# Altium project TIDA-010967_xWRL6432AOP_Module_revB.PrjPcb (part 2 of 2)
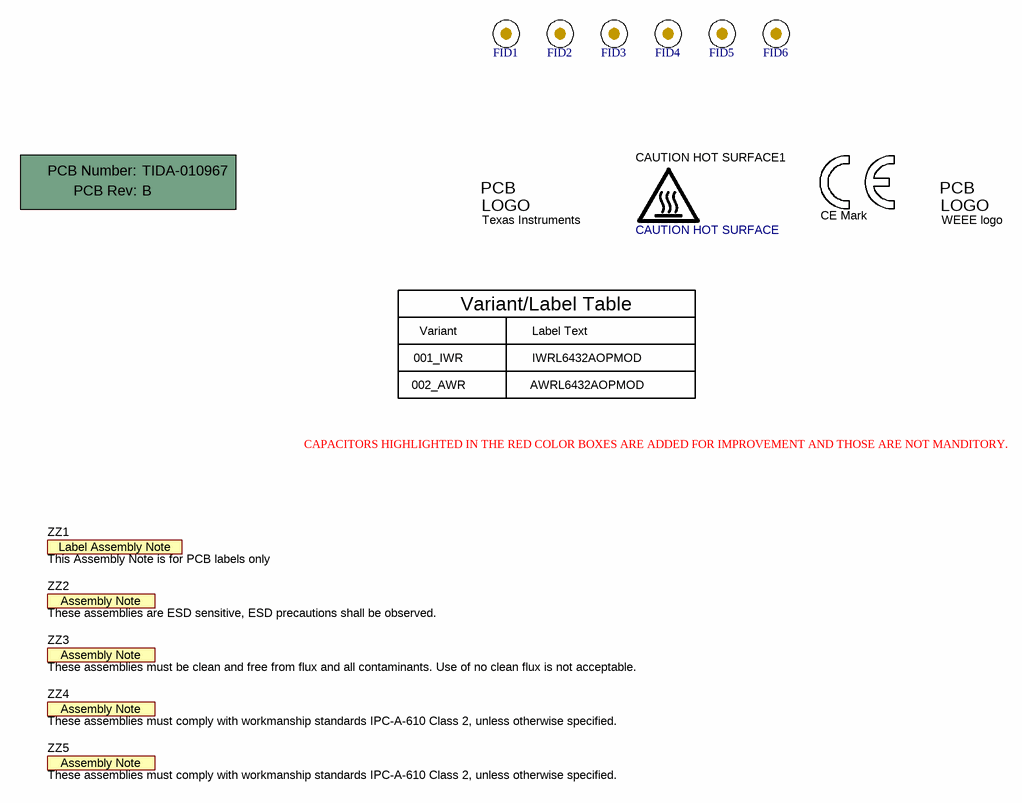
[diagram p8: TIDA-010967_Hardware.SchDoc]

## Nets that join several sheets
5V_IN_USB: TIDA-010967_USB_PWR_Connector (11 pins), TIDA-010967_DC_Regulators (5 pins)
GND: TIDA-010967_USB_PWR_Connector (33 pins), TIDA-010967_DC_Regulators (34 pins), TIDA-010967_xWRL6432_Chip (41 pins), TIDA-010967_Decoupling_caps (15 pins), TIDA-010967_QSPI_Flash (C34.1 C35.2 U3.4 U3.9)
OUT_3V3: TIDA-010967_USB_PWR_Connector (J1.1 J1.2 J1.4 J22.1), TIDA-010967_DC_Regulators (6 pins)
RADAR_1P2_RF: TIDA-010967_xWRL6432_Chip (5 pins), TIDA-010967_Decoupling_caps (C20.2 C44.1)
RADAR_1V2: TIDA-010967_xWRL6432_Chip (TP13.1 U6.K2), TIDA-010967_Decoupling_caps (C27.2)
RADAR_1V4_APLL: TIDA-010967_xWRL6432_Chip (U6.G8), TIDA-010967_Decoupling_caps (C22.1)
RADAR_1V4_SYNTH: TIDA-010967_xWRL6432_Chip (U6.F7), TIDA-010967_Decoupling_caps (C18.1)
RADAR_1V8: TIDA-010967_xWRL6432_Chip (17 pins), TIDA-010967_Decoupling_caps (5 pins)
RADAR_1V_RF_OUT: TIDA-010967_xWRL6432_Chip (5 pins), TIDA-010967_Decoupling_caps (C9.2 C23.1)
RADAR_3V3: TIDA-010967_USB_PWR_Connector (C39.1 R12.1 R19.2 U4.3), TIDA-010967_DC_Regulators (R175.1 TP9.1), TIDA-010967_xWRL6432_Chip (8 pins), TIDA-010967_Decoupling_caps (C17.2 C21.1 L7.2 R11.2), TIDA-010967_QSPI_Flash (6 pins)
RADAR_SRAM_1V2: TIDA-010967_xWRL6432_Chip (U6.M1 U6.M2 U6.N2), TIDA-010967_Decoupling_caps (C5.2 C26.1)
RADAR_VBGAP: TIDA-010967_xWRL6432_Chip (U6.H10), TIDA-010967_Decoupling_caps (C6.1)
REG_1V8: TIDA-010967_DC_Regulators (C11.1 L6.2 TP2.1), TIDA-010967_Decoupling_caps (R6.1)
REG_3V3: TIDA-010967_DC_Regulators (13 pins), TIDA-010967_Decoupling_caps (L7.1)
REG_OUT_1V8: TIDA-010967_USB_PWR_Connector (J24.1), TIDA-010967_DC_Regulators (6 pins)
USB_INPUT_3V3: TIDA-010967_USB_PWR_Connector (J30.1), TIDA-010967_DC_Regulators (5 pins)
GPIO_2: TIDA-010967_USB_PWR_Connector (J8.1), TIDA-010967_xWRL6432_Chip (U6.H2)
GPIO_4: TIDA-010967_DC_Regulators (R7.1), TIDA-010967_xWRL6432_Chip (U6.J4)
HOST_INTR_GPIO_5: TIDA-010967_USB_PWR_Connector (J4.1), TIDA-010967_xWRL6432_Chip (R24.2 U6.J2)
QSPI_CS: TIDA-010967_xWRL6432_Chip (U6.D3), TIDA-010967_QSPI_Flash (R50.2 U3.1)
QSPI_D0: TIDA-010967_xWRL6432_Chip (U6.C2), TIDA-010967_QSPI_Flash (U3.5)
QSPI_D1: TIDA-010967_xWRL6432_Chip (U6.C3), TIDA-010967_QSPI_Flash (U3.2)
QSPI_D2: TIDA-010967_xWRL6432_Chip (U6.C4), TIDA-010967_QSPI_Flash (R44.1 U3.3)
QSPI_D3: TIDA-010967_xWRL6432_Chip (U6.B3 U6.B4), TIDA-010967_QSPI_Flash (R49.1 U3.7)
QSPI_SCLK: TIDA-010967_xWRL6432_Chip (U6.D2), TIDA-010967_QSPI_Flash (U3.6)
RADAR_NRST: TIDA-010967_USB_PWR_Connector (J1.3 J3.1), TIDA-010967_DC_Regulators (R176.1), TIDA-010967_xWRL6432_Chip (C48.2 R165.1 U6.M3 U6.M4)
REG_MODE_SELECT: TIDA-010967_USB_PWR_Connector (J26.1), TIDA-010967_DC_Regulators (6 pins)
RS232_RX: TIDA-010967_USB_PWR_Connector (J1.9 J7.1 J27.1 R17.1), TIDA-010967_xWRL6432_Chip (R74.2 U6.G2)
RS232_TX: TIDA-010967_USB_PWR_Connector (J1.11 J5.1 J31.1 R18.1), TIDA-010967_xWRL6432_Chip (R73.2 U6.H4)
SPI_CLK_I2C_SCL: TIDA-010967_USB_PWR_Connector (J1.20 J13.1), TIDA-010967_xWRL6432_Chip (R75.2 U6.F1)
SPI_CS_I2C_SDA: TIDA-010967_USB_PWR_Connector (J1.17 J15.1), TIDA-010967_xWRL6432_Chip (R4.2 U6.F4)
SPI_MISO_REG_MODE: TIDA-010967_USB_PWR_Connector (J1.19 J17.1), TIDA-010967_xWRL6432_Chip (U6.E4)
SPI_MOSI: TIDA-010967_USB_PWR_Connector (J1.21 J19.1), TIDA-010967_xWRL6432_Chip (U6.E3)
TCK: TIDA-010967_USB_PWR_Connector (J10.1), TIDA-010967_xWRL6432_Chip (TP17.1 U6.F3)
TDI: TIDA-010967_USB_PWR_Connector (J14.1), TIDA-010967_xWRL6432_Chip (TP18.1 U6.F2)
TDO_SOP0: TIDA-010967_USB_PWR_Connector (J1.15 J12.1 R20.1), TIDA-010967_xWRL6432_Chip (R22.1)
TMS: TIDA-010967_USB_PWR_Connector (J6.1), TIDA-010967_xWRL6432_Chip (TP19.1 U6.G3)
UARTA_RX: TIDA-010967_USB_PWR_Connector (J11.1), TIDA-010967_xWRL6432_Chip (U6.J3)
UARTA_TX: TIDA-010967_USB_PWR_Connector (J9.1), TIDA-010967_xWRL6432_Chip (U6.K3)

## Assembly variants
001_IWR: not fitted C2 C19 FID1 FID2 FID3 FID4 FID5 FID6 R2 R11 R12 R23 R24
002_AWR: not fitted C2 C19 FID1 FID2 FID3 FID4 FID5 FID6 R2 R11 R12 R23 R24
